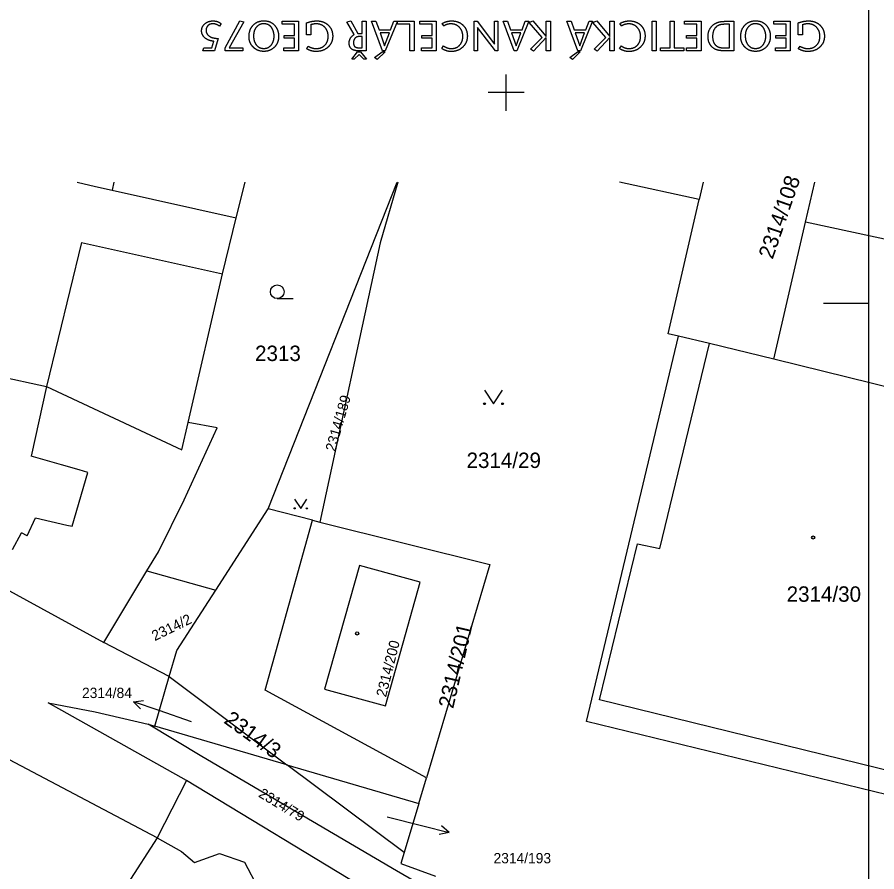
# Model space of a CAD drawing. Extents: x -599970 to -599524, y -1154772 to -1154457.
# Drawn here: x -599627.01 to -599579.53, y -1154593.05 to -1154545.83 of the extents above; entities that cross this region are included whole.
import ezdxf

# ---------------------------------------------------------------- set-up
doc = ezdxf.new("R2010")
doc.units = 0
for name, color, linetype in [('Z-KATASTRALNI MAPA', 7, 'Continuous'), ('Z-KRIZKY CTVERCOVE SITE', 7, 'Continuous'), ('Z-RAM ROZPISKA', 7, 'Continuous')]:
    doc.layers.add(name, color=color, linetype=linetype)

msp = doc.modelspace()

# ---------------------------------------------------------------- linework, layer by layer
at = {"layer": 'Z-KATASTRALNI MAPA'}
for p, q in [((-599621.67, -1154554.95), (-599621.77, -1154555.39)), ((-599614.92, -1154556.92), (-599614.42, -1154554.95)), ((-599613.14, -1154573), (-599606.02, -1154554.95)), ((-599589.34, -1154555.9), (-599593.74, -1154554.95)), ((-599589.12, -1154554.95), (-599589.34, -1154555.9)), ((-599585.22, -1154564.72), (-599583.47, -1154557.16)), ((-599569.35, -1154560.2), (-599583.47, -1154557.16)), ((-599623.45, -1154558.28), (-599625.4, -1154566.23)), ((-599623.45, -1154558.28), (-599615.67, -1154560.02)), ((-599612.647, -1154561.38), (-599611.772, -1154561.38)), ((-599591.52, -1154575.18), (-599588.77, -1154563.87)), ((-599634.54, -1154564.27), (-599625.4, -1154566.23)), ((-599571.91, -1154568.01), (-599585.22, -1154564.72)), ((-599625.4, -1154566.23), (-599626.23, -1154570.09)), ((-599615.96, -1154568.53), (-599617.56, -1154568.22)), ((-599617.79, -1154572.5), (-599615.96, -1154568.53)), ((-599624.57, -1154570.56), (-599626.23, -1154570.09)), ((-599623.59, -1154570.84), (-599624.57, -1154570.56)), ((-599623.97, -1154573.95), (-599623.11, -1154570.98)), ((-599623.11, -1154570.98), (-599623.59, -1154570.84)), ((-599616.04, -1154577.49), (-599613.14, -1154573)), ((-599610.69, -1154573.63), (-599613.14, -1154573)), ((-599626.45, -1154574.49), (-599626, -1154573.49)), ((-599626, -1154573.49), (-599624.27, -1154573.9)), ((-599624.27, -1154573.9), (-599623.97, -1154573.95)), ((-599610.69, -1154573.63), (-599610.29, -1154573.73)), ((-599627.26, -1154575.25), (-599626.77, -1154574.32)), ((-599626.45, -1154574.49), (-599626.77, -1154574.32)), ((-599594.85, -1154583.55), (-599592.75, -1154574.93)), ((-599592.75, -1154574.93), (-599591.52, -1154575.18)), ((-599622.22, -1154580.39), (-599619.85, -1154576.43)), ((-599619.85, -1154576.43), (-599616.04, -1154577.49)), ((-599618.19, -1154580.82), (-599616.04, -1154577.49)), ((-599618.61, -1154582.26), (-599622.22, -1154580.39)), ((-599619.28, -1154591.18), (-599638.67, -1154580.93)), ((-599618.61, -1154582.26), (-599618.19, -1154580.82)), ((-599619.41, -1154585), (-599618.61, -1154582.26)), ((-599618.61, -1154582.26), (-599612.11, -1154587.14)), ((-599577.82, -1154587.73), (-599594.85, -1154583.55)), ((-599617.65, -1154588), (-599625.3, -1154583.72)), ((-599620.588, -1154583.651), (-599620.034, -1154583.578)), ((-599619.17, -1154584.14), (-599620.588, -1154583.651)), ((-599620.588, -1154583.651), (-599620.197, -1154584.051)), ((-599617.38, -1154584.76), (-599619.17, -1154584.14)), ((-599619.77, -1154584.89), (-599619.41, -1154585)), ((-599612.11, -1154587.14), (-599619.41, -1154585)), ((-599605.64, -1154591.99), (-599612.11, -1154587.14)), ((-599612.11, -1154587.14), (-599604.83, -1154589.27)), ((-599617.65, -1154588), (-599619.28, -1154591.18)), ((-599607.38, -1154594.23), (-599617.65, -1154588)), ((-599604.83, -1154589.27), (-599604.41, -1154587.85)), ((-599604.83, -1154589.27), (-599605.64, -1154591.99)), ((-599606.57, -1154590.01), (-599604.61, -1154590.51)), ((-599604.61, -1154590.51), (-599603.154, -1154590.873)), ((-599603.154, -1154590.873), (-599603.579, -1154590.509)), ((-599603.154, -1154590.873), (-599603.701, -1154590.995)), ((-599619.28, -1154591.18), (-599617.93, -1154591.92)), ((-599617.93, -1154591.92), (-599617.21, -1154592.53)), ((-599617.21, -1154592.53), (-599615.84, -1154592.03)), ((-599615.84, -1154592.03), (-599614.46, -1154592.51)), ((-599614.46, -1154592.51), (-599613.7, -1154593.96))]:
    msp.add_line(p, q, dxfattribs=at)
for points in [[(-599623.7, -1154554.95), (-599622.69, -1154555.18), (-599621.77, -1154555.39), (-599614.92, -1154556.92)], [(-599605.99, -1154554.95), (-599606.97, -1154558.3), (-599610.29, -1154573.73)], [(-599583.47, -1154557.16), (-599582.96, -1154554.95)], [(-599590.49, -1154563.45), (-599591.05, -1154563.32), (-599589.34, -1154555.9)], [(-599617.56, -1154568.22), (-599615.67, -1154560.02), (-599614.92, -1154556.92)], [(-599578.2, -1154588.98), (-599595.57, -1154584.75), (-599590.49, -1154563.45)], [(-599585.22, -1154564.72), (-599588.77, -1154563.87), (-599590.49, -1154563.45)], [(-599625.4, -1154566.23), (-599617.91, -1154569.73), (-599617.56, -1154568.22)], [(-599601.2, -1154566.44), (-599600.7, -1154567.19), (-599600.2, -1154566.44)], [(-599636.38, -1154571.9), (-599636.13, -1154572.03), (-599635.35, -1154573.38), (-599633.04, -1154573.91), (-599633.71, -1154574.25), (-599628.23, -1154577.1), (-599626.49, -1154578.05), (-599622.22, -1154580.39)], [(-599619.85, -1154576.43), (-599619.21, -1154575.37), (-599617.79, -1154572.5)], [(-599611.685, -1154572.467), (-599611.35, -1154572.97), (-599611.015, -1154572.467)], [(-599604.41, -1154587.85), (-599613.32, -1154583.01), (-599610.69, -1154573.63)], [(-599610.29, -1154573.73), (-599600.91, -1154576.08), (-599604.41, -1154587.85)], [(-599608.11, -1154576.13), (-599610.03, -1154582.96), (-599606.66, -1154583.88), (-599604.76, -1154577.05), (-599608.11, -1154576.13)], [(-599625.3, -1154583.72), (-599622.71, -1154584.21), (-599619.77, -1154584.89)], [(-599583.46, -1154606.09), (-599606.05, -1154592.99), (-599616.82, -1154586.68), (-599619.77, -1154584.89)], [(-599619.28, -1154591.18), (-599622.56, -1154596.26), (-599624.56, -1154599.26)], [(-599605.64, -1154591.99), (-599605.82, -1154592.59), (-599603.91, -1154593.29)]]:
    msp.add_lwpolyline(points, dxfattribs=at)
for centre, radius in [((-599612.646, -1154561.005), 0.375), ((-599601.2, -1154567.19), 0.05), ((-599600.2, -1154567.19), 0.05), ((-599611.685, -1154572.97), 0.0335), ((-599611.015, -1154572.97), 0.0335), ((-599583.043, -1154574.58), 0.0875), ((-599608.233, -1154579.88), 0.0875)]:
    msp.add_circle(centre, radius, dxfattribs=at)
at = {"layer": 'Z-KRIZKY CTVERCOVE SITE'}
for p, q in [((-599600, -1154551), (-599600, -1154549)), ((-599599, -1154550), (-599601, -1154550))]:
    msp.add_line(p, q, dxfattribs=at)
at = {"layer": 'Z-RAM ROZPISKA'}
msp.add_line((-599579.98, -1154561.65), (-599582.48, -1154561.65), dxfattribs=at)
msp.add_lwpolyline([(-599876.98, -1154456.65), (-599579.98, -1154456.65), (-599579.98, -1154771.65), (-599876.98, -1154771.65)], close=True, dxfattribs=at)
for points in [[(-599614.54, -1154547.69), (-599615.53, -1154547.69), (-599615.53, -1154547.52), (-599614.71, -1154546.04), (-599614.5, -1154546.09), (-599615.31, -1154547.52), (-599614.54, -1154547.52), (-599614.54, -1154547.69)], [(-599608.399, -1154546.794), (-599608.808, -1154546.099), (-599608.577, -1154546.028), (-599608.199, -1154546.733), (-599607.961, -1154546.733), (-599607.961, -1154546.057), (-599607.731, -1154546.057)], [(-599597.56, -1154546.06), (-599597.56, -1154547.69), (-599597.79, -1154547.69), (-599597.79, -1154546.96), (-599598.5, -1154547.72), (-599598.66, -1154547.61), (-599598.02, -1154546.95), (-599598.74, -1154546.12), (-599598.52, -1154546.03), (-599597.79, -1154546.91), (-599597.79, -1154546.06), (-599597.56, -1154546.06)], [(-599594.04, -1154546.06), (-599594.04, -1154547.69), (-599594.27, -1154547.69), (-599594.27, -1154546.96), (-599594.98, -1154547.72), (-599595.14, -1154547.61), (-599594.5, -1154546.95), (-599595.22, -1154546.12), (-599595, -1154546.03), (-599594.27, -1154546.91), (-599594.27, -1154546.06), (-599594.04, -1154546.06)], [(-599615.75, -1154546.18), (-599615.83, -1154546.33)], [(-599611.47, -1154546.06), (-599611.47, -1154547.69), (-599612.29, -1154547.69), (-599612.29, -1154547.53), (-599611.7, -1154547.53), (-599611.7, -1154547), (-599612.27, -1154547), (-599612.27, -1154546.84), (-599611.7, -1154546.84), (-599611.7, -1154546.22), (-599612.38, -1154546.22), (-599612.38, -1154546.06), (-599611.47, -1154546.06)], [(-599610.8, -1154546.81), (-599611.03, -1154546.81), (-599611.03, -1154546.14)], [(-599610.8, -1154546.25), (-599610.8, -1154546.81)], [(-599607.731, -1154546.057), (-599607.731, -1154547.693), (-599608.115, -1154547.693)], [(-599607.025, -1154546.542), (-599606.39, -1154546.542), (-599606.212, -1154546.061), (-599606.009, -1154546.061), (-599606.679, -1154547.696), (-599606.829, -1154547.696), (-599607.441, -1154546.061), (-599607.194, -1154546.061), (-599607.025, -1154546.542)], [(-599605.09, -1154546.06), (-599605.09, -1154547.69), (-599605.32, -1154547.69), (-599605.32, -1154546.22), (-599606, -1154546.22), (-599606, -1154546.06), (-599605.09, -1154546.06)], [(-599603.86, -1154546.06), (-599603.86, -1154547.69), (-599604.67, -1154547.69), (-599604.67, -1154547.53), (-599604.09, -1154547.53), (-599604.09, -1154547), (-599604.66, -1154547), (-599604.66, -1154546.84), (-599604.09, -1154546.84), (-599604.09, -1154546.22), (-599604.77, -1154546.22), (-599604.77, -1154546.06), (-599603.86, -1154546.06)], [(-599603.44, -1154546.31), (-599603.53, -1154546.18)], [(-599600.46, -1154546.06), (-599600.46, -1154547.69), (-599600.6, -1154547.69), (-599601.58, -1154546.41), (-599601.58, -1154547.69), (-599601.77, -1154547.69), (-599601.77, -1154546.06), (-599601.61, -1154546.06), (-599600.64, -1154547.33), (-599600.64, -1154546.06), (-599600.46, -1154546.06)], [(-599599.76, -1154546.542), (-599599.125, -1154546.542), (-599598.947, -1154546.061), (-599598.744, -1154546.061), (-599599.414, -1154547.696), (-599599.564, -1154547.696), (-599600.176, -1154546.061), (-599599.929, -1154546.061), (-599599.76, -1154546.542)], [(-599596.24, -1154546.542), (-599595.605, -1154546.542), (-599595.426, -1154546.061), (-599595.224, -1154546.061), (-599595.894, -1154547.696), (-599596.043, -1154547.696), (-599596.656, -1154546.061), (-599596.409, -1154546.061), (-599596.24, -1154546.542)], [(-599593.63, -1154546.31), (-599593.72, -1154546.18)], [(-599591.71, -1154546.06), (-599591.71, -1154547.69), (-599591.94, -1154547.69), (-599591.94, -1154546.06), (-599591.71, -1154546.06)], [(-599590.72, -1154546.06), (-599590.72, -1154547.53), (-599590.19, -1154547.53), (-599590.19, -1154547.69), (-599591.47, -1154547.69), (-599591.47, -1154547.53), (-599590.95, -1154547.53), (-599590.95, -1154546.06), (-599590.72, -1154546.06)], [(-599589.24, -1154546.06), (-599589.24, -1154547.69), (-599590.05, -1154547.69), (-599590.05, -1154547.53), (-599589.47, -1154547.53), (-599589.47, -1154547), (-599590.04, -1154547), (-599590.04, -1154546.84), (-599589.47, -1154546.84), (-599589.47, -1154546.22), (-599590.15, -1154546.22), (-599590.15, -1154546.06), (-599589.24, -1154546.06)], [(-599587.433, -1154546.061), (-599587.433, -1154547.696), (-599587.846, -1154547.696)], [(-599587.844, -1154547.532), (-599587.663, -1154547.532), (-599587.663, -1154546.225)], [(-599587.831, -1154546.061), (-599587.433, -1154546.061)], [(-599587.663, -1154546.225), (-599587.831, -1154546.225)], [(-599584.31, -1154546.06), (-599584.31, -1154547.69), (-599585.12, -1154547.69), (-599585.12, -1154547.53), (-599584.54, -1154547.53), (-599584.54, -1154547), (-599585.11, -1154547), (-599585.11, -1154546.84), (-599584.54, -1154546.84), (-599584.54, -1154546.22), (-599585.22, -1154546.22), (-599585.22, -1154546.06), (-599584.31, -1154546.06)], [(-599583.64, -1154546.81), (-599583.87, -1154546.81), (-599583.87, -1154546.14)], [(-599583.64, -1154546.25), (-599583.64, -1154546.81)], [(-599608.108, -1154547.528), (-599607.961, -1154547.528), (-599607.961, -1154546.898)], [(-599607.961, -1154546.898), (-599608.063, -1154546.898)], [(-599606.97, -1154546.705), (-599606.722, -1154547.408), (-599606.453, -1154546.705), (-599606.97, -1154546.705)], [(-599599.705, -1154546.705), (-599599.457, -1154547.408), (-599599.188, -1154546.705), (-599599.705, -1154546.705)], [(-599596.185, -1154546.705), (-599595.937, -1154547.408), (-599595.667, -1154546.705), (-599596.185, -1154546.705)], [(-599616.11, -1154547.69), (-599616.75, -1154547.69), (-599616.7, -1154547.52), (-599616.26, -1154547.52), (-599616.15, -1154547.16)], [(-599615.91, -1154547.01), (-599616.11, -1154547.69)], [(-599611.02, -1154547.56), (-599610.93, -1154547.43)], [(-599603.56, -1154547.56), (-599603.46, -1154547.42)], [(-599593.74, -1154547.56), (-599593.64, -1154547.42)], [(-599583.86, -1154547.56), (-599583.77, -1154547.43)], [(-599608.13, -1154547.9), (-599608.39, -1154548.15), (-599608.53, -1154548.15), (-599608.21, -1154547.74), (-599608.05, -1154547.74), (-599607.72, -1154548.15), (-599607.87, -1154548.15), (-599608.13, -1154547.9)], [(-599606.85, -1154547.74), (-599606.69, -1154547.74), (-599607.12, -1154548.18), (-599607.28, -1154548.06), (-599606.85, -1154547.74)], [(-599596.06, -1154547.74), (-599595.91, -1154547.74), (-599596.34, -1154548.18), (-599596.49, -1154548.06), (-599596.06, -1154547.74)]]:
    msp.add_lwpolyline(points, dxfattribs=at)
for points in [[(-599616.642, -1154546.196), (-599616.461, -1154546.039), (-599616.188, -1154546.039)], [(-599616.188, -1154546.039), (-599615.928, -1154546.039), (-599615.752, -1154546.19)], [(-599613.978, -1154546.277), (-599613.75, -1154546.033), (-599613.388, -1154546.033)], [(-599613.388, -1154546.033), (-599612.965, -1154546.033), (-599612.739, -1154546.348)], [(-599611.036, -1154546.148), (-599610.718, -1154546.039), (-599610.459, -1154546.039)], [(-599610.459, -1154546.039), (-599610.071, -1154546.039), (-599609.827, -1154546.275)], [(-599603.538, -1154546.187), (-599603.305, -1154546.039), (-599603.003, -1154546.039)], [(-599603.003, -1154546.039), (-599602.63, -1154546.039), (-599602.388, -1154546.274)], [(-599593.722, -1154546.187), (-599593.49, -1154546.039), (-599593.188, -1154546.039)], [(-599593.188, -1154546.039), (-599592.814, -1154546.039), (-599592.572, -1154546.274)], [(-599586.819, -1154546.277), (-599586.591, -1154546.033), (-599586.229, -1154546.033)], [(-599586.229, -1154546.033), (-599585.806, -1154546.033), (-599585.58, -1154546.348)], [(-599583.876, -1154546.148), (-599583.557, -1154546.039), (-599583.298, -1154546.039)], [(-599583.298, -1154546.039), (-599582.911, -1154546.039), (-599582.667, -1154546.275)], [(-599616.824, -1154546.584), (-599616.824, -1154546.352), (-599616.642, -1154546.196)], [(-599616.473, -1154546.301), (-599616.577, -1154546.403), (-599616.577, -1154546.558)], [(-599616.211, -1154546.2), (-599616.369, -1154546.2), (-599616.473, -1154546.301)], [(-599615.833, -1154546.336), (-599616.004, -1154546.2), (-599616.211, -1154546.2)], [(-599614.206, -1154546.908), (-599614.206, -1154546.521), (-599613.978, -1154546.277)], [(-599613.798, -1154546.387), (-599613.955, -1154546.575), (-599613.955, -1154546.879)], [(-599613.388, -1154546.198), (-599613.641, -1154546.198), (-599613.798, -1154546.387)], [(-599613.007, -1154546.351), (-599613.152, -1154546.198), (-599613.388, -1154546.198)], [(-599612.871, -1154546.585), (-599612.922, -1154546.441), (-599613.007, -1154546.351)], [(-599612.739, -1154546.348), (-599612.57, -1154546.585), (-599612.57, -1154546.895)], [(-599610.505, -1154546.202), (-599610.652, -1154546.202), (-599610.807, -1154546.261)], [(-599610.018, -1154546.394), (-599610.203, -1154546.202), (-599610.505, -1154546.202)], [(-599609.834, -1154546.901), (-599609.834, -1154546.586), (-599610.018, -1154546.394)], [(-599609.827, -1154546.275), (-599609.583, -1154546.511), (-599609.583, -1154546.885)], [(-599603.048, -1154546.204), (-599603.268, -1154546.204), (-599603.448, -1154546.322)], [(-599602.58, -1154546.398), (-599602.764, -1154546.204), (-599603.048, -1154546.204)], [(-599602.396, -1154546.892), (-599602.396, -1154546.593), (-599602.58, -1154546.398)], [(-599602.388, -1154546.274), (-599602.146, -1154546.509), (-599602.146, -1154546.873)], [(-599593.232, -1154546.204), (-599593.452, -1154546.204), (-599593.632, -1154546.322)], [(-599592.764, -1154546.398), (-599592.948, -1154546.204), (-599593.232, -1154546.204)], [(-599592.58, -1154546.892), (-599592.58, -1154546.593), (-599592.764, -1154546.398)], [(-599592.572, -1154546.274), (-599592.33, -1154546.509), (-599592.33, -1154546.873)], [(-599588.85, -1154546.913), (-599588.85, -1154546.432), (-599588.492, -1154546.205)], [(-599588.37, -1154546.348), (-599588.6, -1154546.52), (-599588.6, -1154546.902)], [(-599588.492, -1154546.205), (-599588.366, -1154546.124), (-599588.219, -1154546.093)], [(-599588.162, -1154546.251), (-599588.275, -1154546.277), (-599588.37, -1154546.348)], [(-599588.219, -1154546.093), (-599588.073, -1154546.061), (-599587.831, -1154546.061)], [(-599587.831, -1154546.225), (-599588.049, -1154546.225), (-599588.162, -1154546.251)], [(-599587.046, -1154546.908), (-599587.046, -1154546.521), (-599586.819, -1154546.277)], [(-599586.639, -1154546.387), (-599586.796, -1154546.575), (-599586.796, -1154546.879)], [(-599586.229, -1154546.198), (-599586.482, -1154546.198), (-599586.639, -1154546.387)], [(-599585.848, -1154546.351), (-599585.993, -1154546.198), (-599586.229, -1154546.198)], [(-599585.712, -1154546.585), (-599585.763, -1154546.441), (-599585.848, -1154546.351)], [(-599585.58, -1154546.348), (-599585.411, -1154546.585), (-599585.411, -1154546.895)], [(-599583.345, -1154546.202), (-599583.492, -1154546.202), (-599583.647, -1154546.261)], [(-599582.858, -1154546.394), (-599583.042, -1154546.202), (-599583.345, -1154546.202)], [(-599582.673, -1154546.901), (-599582.673, -1154546.586), (-599582.858, -1154546.394)], [(-599582.667, -1154546.275), (-599582.423, -1154546.511), (-599582.423, -1154546.885)], [(-599616.745, -1154546.855), (-599616.824, -1154546.728), (-599616.824, -1154546.584)], [(-599616.526, -1154547.059), (-599616.667, -1154546.981), (-599616.745, -1154546.855)], [(-599616.577, -1154546.558), (-599616.577, -1154546.822), (-599616.288, -1154546.941)], [(-599616.288, -1154546.941), (-599616.164, -1154546.992), (-599615.914, -1154547.019)], [(-599613.971, -1154547.49), (-599614.206, -1154547.256), (-599614.206, -1154546.908)], [(-599613.955, -1154546.879), (-599613.955, -1154547.184), (-599613.798, -1154547.372)], [(-599612.978, -1154547.372), (-599612.82, -1154547.182), (-599612.82, -1154546.879)], [(-599612.82, -1154546.879), (-599612.82, -1154546.728), (-599612.871, -1154546.585)], [(-599612.57, -1154546.895), (-599612.57, -1154547.252), (-599612.802, -1154547.488)], [(-599610.02, -1154547.384), (-599609.834, -1154547.201), (-599609.834, -1154546.901)], [(-599609.583, -1154546.885), (-599609.583, -1154547.253), (-599609.844, -1154547.492)], [(-599608.675, -1154547.267), (-599608.675, -1154546.97), (-599608.399, -1154546.794)], [(-599608.34, -1154546.987), (-599608.435, -1154547.076), (-599608.435, -1154547.248)], [(-599608.063, -1154546.898), (-599608.245, -1154546.898), (-599608.34, -1154546.987)], [(-599602.572, -1154547.382), (-599602.396, -1154547.198), (-599602.396, -1154546.892)], [(-599602.146, -1154546.873), (-599602.146, -1154547.24), (-599602.401, -1154547.486)], [(-599592.756, -1154547.382), (-599592.58, -1154547.198), (-599592.58, -1154546.892)], [(-599592.33, -1154546.873), (-599592.33, -1154547.24), (-599592.586, -1154547.486)], [(-599588.557, -1154547.543), (-599588.85, -1154547.326), (-599588.85, -1154546.913)], [(-599588.6, -1154546.902), (-599588.6, -1154547.285), (-599588.356, -1154547.44)], [(-599586.812, -1154547.49), (-599587.046, -1154547.256), (-599587.046, -1154546.908)], [(-599586.796, -1154546.879), (-599586.796, -1154547.184), (-599586.639, -1154547.372)], [(-599585.819, -1154547.372), (-599585.661, -1154547.182), (-599585.661, -1154546.879)], [(-599585.661, -1154546.879), (-599585.661, -1154546.728), (-599585.712, -1154546.585)], [(-599585.411, -1154546.895), (-599585.411, -1154547.252), (-599585.643, -1154547.488)], [(-599582.859, -1154547.384), (-599582.673, -1154547.201), (-599582.673, -1154546.901)], [(-599582.423, -1154546.885), (-599582.423, -1154547.253), (-599582.684, -1154547.492)], [(-599616.157, -1154547.169), (-599616.402, -1154547.131), (-599616.526, -1154547.059)], [(-599613.798, -1154547.372), (-599613.641, -1154547.561), (-599613.388, -1154547.561)], [(-599613.388, -1154547.561), (-599613.135, -1154547.561), (-599612.978, -1154547.372)], [(-599610.93, -1154547.438), (-599610.719, -1154547.567), (-599610.51, -1154547.567)], [(-599610.51, -1154547.567), (-599610.205, -1154547.567), (-599610.02, -1154547.384)], [(-599608.51, -1154547.611), (-599608.675, -1154547.492), (-599608.675, -1154547.267)], [(-599608.435, -1154547.248), (-599608.435, -1154547.398), (-599608.359, -1154547.463)], [(-599608.359, -1154547.463), (-599608.283, -1154547.528), (-599608.108, -1154547.528)], [(-599603.462, -1154547.424), (-599603.25, -1154547.567), (-599603.039, -1154547.567)], [(-599603.039, -1154547.567), (-599602.748, -1154547.567), (-599602.572, -1154547.382)], [(-599593.646, -1154547.424), (-599593.434, -1154547.567), (-599593.224, -1154547.567)], [(-599593.224, -1154547.567), (-599592.932, -1154547.567), (-599592.756, -1154547.382)], [(-599588.356, -1154547.44), (-599588.269, -1154547.494), (-599588.164, -1154547.513)], [(-599586.639, -1154547.372), (-599586.482, -1154547.561), (-599586.229, -1154547.561)], [(-599586.229, -1154547.561), (-599585.976, -1154547.561), (-599585.819, -1154547.372)], [(-599583.769, -1154547.438), (-599583.558, -1154547.567), (-599583.35, -1154547.567)], [(-599583.35, -1154547.567), (-599583.045, -1154547.567), (-599582.859, -1154547.384)], [(-599613.388, -1154547.724), (-599613.736, -1154547.724), (-599613.971, -1154547.49)], [(-599612.802, -1154547.488), (-599613.035, -1154547.724), (-599613.388, -1154547.724)], [(-599610.508, -1154547.73), (-599610.784, -1154547.73), (-599611.024, -1154547.573)], [(-599609.844, -1154547.492), (-599610.105, -1154547.73), (-599610.508, -1154547.73)], [(-599608.115, -1154547.693), (-599608.397, -1154547.693), (-599608.51, -1154547.611)], [(-599603.039, -1154547.731), (-599603.309, -1154547.731), (-599603.559, -1154547.567)], [(-599602.401, -1154547.486), (-599602.657, -1154547.731), (-599603.039, -1154547.731)], [(-599593.224, -1154547.731), (-599593.493, -1154547.731), (-599593.744, -1154547.567)], [(-599592.586, -1154547.486), (-599592.841, -1154547.731), (-599593.224, -1154547.731)], [(-599588.285, -1154547.662), (-599588.443, -1154547.628), (-599588.557, -1154547.543)], [(-599587.846, -1154547.696), (-599588.127, -1154547.696), (-599588.285, -1154547.662)], [(-599588.164, -1154547.513), (-599588.06, -1154547.532), (-599587.844, -1154547.532)], [(-599586.229, -1154547.724), (-599586.577, -1154547.724), (-599586.812, -1154547.49)], [(-599585.643, -1154547.488), (-599585.876, -1154547.724), (-599586.229, -1154547.724)], [(-599583.347, -1154547.73), (-599583.623, -1154547.73), (-599583.864, -1154547.573)], [(-599582.684, -1154547.492), (-599582.945, -1154547.73), (-599583.347, -1154547.73)]]:
    msp.add_open_spline(points, degree=2, dxfattribs=at)

# ---------------------------------------------------------------- texts
at = {"layer": 'Z-KATASTRALNI MAPA'}
for s, height, rotation, p in [('2314/108', 0.85, 71, (-599585.286, -1154559.25)), ('2314/189', 0.57, 74, (-599609.451, -1154569.869)), ('2314/2', 0.57, 26, (-599619.408, -1154580.309)), ('2314/201', 0.85, 77, (-599602.93, -1154584.068)), ('2314/200', 0.5695, 76, (-599606.64, -1154583.43)), ('2314/3', 0.85, 324, (-599615.647, -1154584.788)), ('2314/79', 0.57, 329, (-599613.728, -1154588.878))]:
    msp.add_text(s, height=height, rotation=rotation, dxfattribs=at).set_placement(p)
for s, height, p in [('2313', 0.85, (-599613.872, -1154564.83)), ('2314/29', 0.85, (-599602.189, -1154570.74)), ('2314/30', 0.85, (-599584.509, -1154578.13)), ('2314/84', 0.57, (-599623.429, -1154583.45)), ('2314/193', 0.57, (-599600.7, -1154592.58))]:
    msp.add_text(s, height=height, dxfattribs=at).set_placement(p)

doc.saveas('drawing.dxf')
